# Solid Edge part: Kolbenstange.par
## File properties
Last saved by: bmolnar
Revision: 77
Sűrűség: 0,000 kg/m^3
Pontosság: 0,990
Dokumentum tartalom típus: 0
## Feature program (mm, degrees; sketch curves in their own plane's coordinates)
base feature "unnamed BaseFeature 1"
sketch for "unnamed Protrusion 1" plane through (0, 0, -16.4) normal (0, 0, -1) x-axis (0, 1, 0)
  circle centre (0, 0) radius 16
extrude "unnamed Protrusion 1" add finite 18.25 along +normal
sketch for "Kihúzás_2" #1 plane through (0, 0, -16.4) normal (0, 0, -1) x-axis (0, 1, 0)
  circle centre (0, 0) radius 6
sketch for "Kihúzás_2" #2 plane through (0, 0, -16.4) normal (0, 0, -1) x-axis (0, 1, 0)
  circle centre (0, 0) radius 16
extrude "Kihúzás_2" add finite 12.35 along -normal
sketch for "Furat_1" plane through (0, 0, 13.9) normal (0, 0, 1) x-axis (1, 0, 0)
hole "Furat_1" diameter 4.92 finite  VBottomAngle = 118 deg
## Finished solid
Body 1: solid body, 16 faces, 22 edges, 12 vertices.
  Faces by surface: plane 8, cylinder 4, cone 2, torus 2
  Edges by curve: circle 12, line 6, curve on surface 2, ellipse 2
Bounding box of the edges (mm; curved faces can reach further): 32.000 x 32.000 x 51.050, from (-16, -16, -34.65) to (16, 16, 16.4).
Cylindrical faces by radius (mm): R2.46 x1, R3.125 x1, R6 x1, R16 x1
Conical faces (half-angle, radius in mm at the cone's reference point): 45 deg R3.225 x1, 59 deg R2.46 x1
Toroidal faces (ring radius, tube radius in mm): R2.725 r0.4 x1, R4.7 r1.3 x1
Planar faces by outward normal: +x 1, +z 3, -x 1, -z 1, oblique 2
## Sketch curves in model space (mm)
circle centre (0, 0, -16.4) radius 16
circle centre (0, 0, -16.4) radius 6
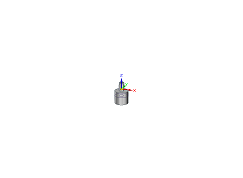
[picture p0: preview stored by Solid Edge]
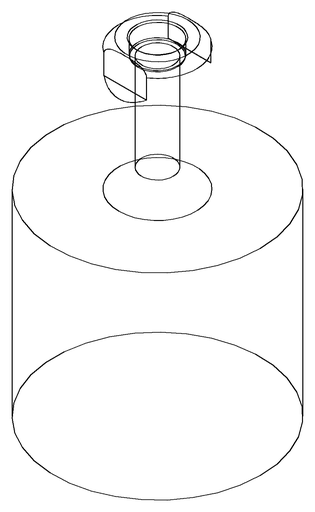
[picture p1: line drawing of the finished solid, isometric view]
